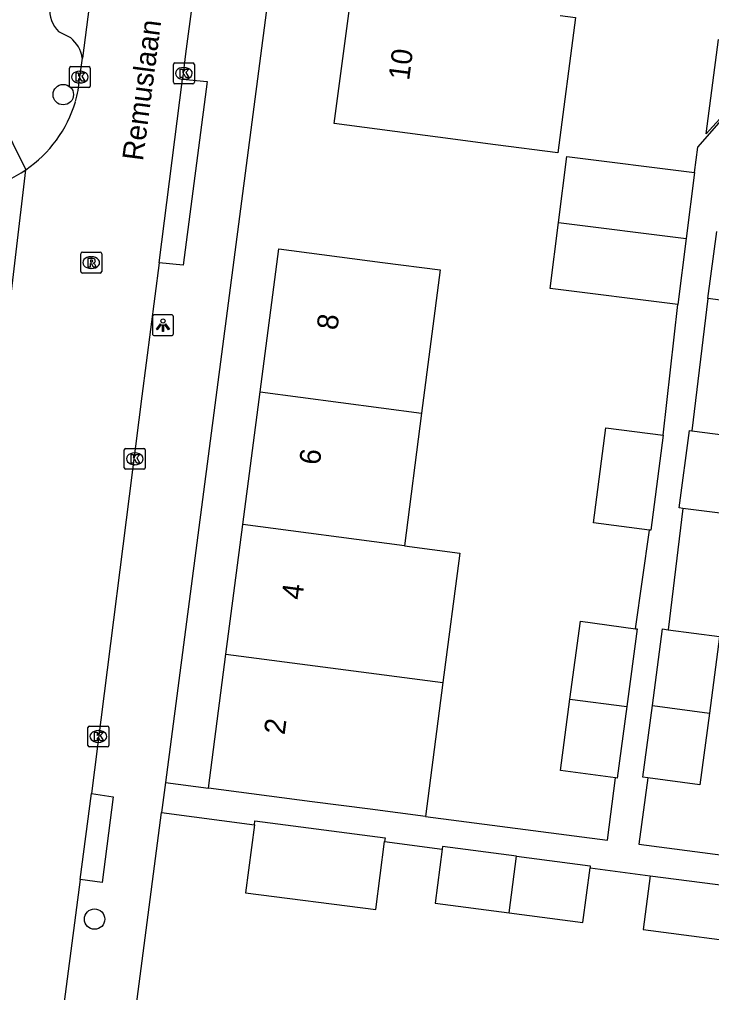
# Model space of a CAD drawing. Extents: x 162186 to 163152, y 385513 to 386513.
# Drawn here: x 162511.74 to 162544.83, y 386146.91 to 386193.42 of the extents above; entities that cross this region are included whole.
import ezdxf

# ---------------------------------------------------------------- set-up
doc = ezdxf.new("R2010")
doc.units = 0
for name, color, linetype in [('IMGEO_Boom', 7, 'Continuous'), ('IMGEO_Kolk', 7, 'Continuous'), ('IMGEO_Lichtpunt', 7, 'Continuous'), ('IMGEO_Openbare_ruimte_label', 7, 'Continuous'), ('IMGEO_Pand', 7, 'Continuous'), ('IMGEO_Pand_nummerreeks', 7, 'Continuous'), ('IMGEO_Rijbaan_lokaal_open', 7, 'Continuous'), ('IMGEO_Rioolput', 7, 'Continuous'), ('IMGEO_Voetpad_open', 7, 'Continuous')]:
    doc.layers.add(name, color=color, linetype=linetype)

msp = doc.modelspace()

# ---------------------------------------------------------------- linework, layer by layer
at = {"layer": 'IMGEO_Boom'}
for centre in [(162513.834, 386189.826), (162515.331, 386150.42)]:
    msp.add_circle(centre, 0.489, dxfattribs=at)
at = {"layer": 'IMGEO_Kolk'}
for p, q in [((162519.1, 386190.415), (162519.1, 386191.267)), ((162519.175, 386191.341), (162520.027, 386191.341)), ((162520.101, 386191.267), (162520.101, 386190.415)), ((162514.126, 386190.238), (162514.126, 386191.09)), ((162514.201, 386191.164), (162515.053, 386191.164)), ((162514.614, 386190.944), (162514.639, 386190.944)), ((162515.127, 386191.09), (162515.127, 386190.238)), ((162519.588, 386191.121), (162519.613, 386191.121)), ((162514.637, 386190.384), (162514.612, 386190.384)), ((162520.027, 386190.341), (162519.175, 386190.341)), ((162519.611, 386190.561), (162519.586, 386190.561)), ((162515.053, 386190.164), (162514.201, 386190.164)), ((162516.753, 386171.993), (162516.753, 386172.845)), ((162516.828, 386172.919), (162517.68, 386172.919)), ((162517.241, 386172.699), (162517.266, 386172.699)), ((162517.754, 386172.845), (162517.754, 386171.993)), ((162517.68, 386171.919), (162516.828, 386171.919)), ((162517.264, 386172.139), (162517.239, 386172.139)), ((162515.087, 386159.648), (162515.939, 386159.648)), ((162515.012, 386158.722), (162515.012, 386159.574)), ((162515.5, 386159.428), (162515.525, 386159.428)), ((162516.013, 386159.574), (162516.013, 386158.722)), ((162515.523, 386158.868), (162515.498, 386158.868)), ((162515.939, 386158.648), (162515.087, 386158.648))]:
    msp.add_line(p, q, dxfattribs=at)
for points in [[(162519.1, 386190.415), (162519.1, 386191.267)], [(162519.175, 386191.341), (162520.027, 386191.341)], [(162520.101, 386191.267), (162520.101, 386190.415)], [(162514.126, 386190.238), (162514.126, 386191.09)], [(162514.201, 386191.164), (162515.053, 386191.164)], [(162514.447, 386190.864), (162514.57, 386190.864), (162514.57, 386190.713), (162514.7, 386190.864), (162514.864, 386190.864), (162514.718, 386190.713), (162514.871, 386190.464), (162514.719, 386190.464), (162514.634, 386190.628), (162514.57, 386190.561), (162514.57, 386190.464), (162514.447, 386190.464), (162514.447, 386190.864)], [(162515.127, 386191.09), (162515.127, 386190.238)], [(162519.421, 386191.041), (162519.544, 386191.041), (162519.544, 386190.89), (162519.674, 386191.041), (162519.838, 386191.041), (162519.692, 386190.89), (162519.845, 386190.641), (162519.693, 386190.641), (162519.608, 386190.805), (162519.544, 386190.738), (162519.544, 386190.641), (162519.421, 386190.641), (162519.421, 386191.041)], [(162520.027, 386190.341), (162519.175, 386190.341)], [(162515.053, 386190.164), (162514.201, 386190.164)], [(162516.753, 386171.993), (162516.753, 386172.845)], [(162516.828, 386172.919), (162517.68, 386172.919)], [(162517.754, 386172.845), (162517.754, 386171.993)], [(162517.074, 386172.619), (162517.197, 386172.619), (162517.197, 386172.468), (162517.327, 386172.619), (162517.491, 386172.619), (162517.345, 386172.468), (162517.498, 386172.219), (162517.346, 386172.219), (162517.261, 386172.383), (162517.197, 386172.316), (162517.197, 386172.219), (162517.074, 386172.219), (162517.074, 386172.619)], [(162517.68, 386171.919), (162516.828, 386171.919)], [(162515.087, 386159.648), (162515.939, 386159.648)], [(162515.012, 386158.722), (162515.012, 386159.574)], [(162515.333, 386159.348), (162515.456, 386159.348), (162515.456, 386159.197), (162515.586, 386159.348), (162515.75, 386159.348), (162515.604, 386159.197), (162515.757, 386158.948), (162515.605, 386158.948), (162515.52, 386159.112), (162515.456, 386159.045), (162515.456, 386158.948), (162515.333, 386158.948), (162515.333, 386159.348)], [(162516.013, 386159.574), (162516.013, 386158.722)], [(162515.939, 386158.648), (162515.087, 386158.648)]]:
    msp.add_lwpolyline(points, dxfattribs=at)
for centre, start, end in [((162519.177, 386191.265), 91.552, 178.448), ((162519.177, 386191.265), 91.552, 178.448), ((162520.025, 386191.265), 1.552, 88.448), ((162520.025, 386191.265), 1.552, 88.448), ((162514.203, 386191.088), 91.552, 178.448), ((162514.203, 386191.088), 91.552, 178.448), ((162515.051, 386191.088), 1.552, 88.448), ((162515.051, 386191.088), 1.552, 88.448), ((162519.177, 386190.417), 181.552, 268.448), ((162519.177, 386190.417), 181.552, 268.448), ((162520.025, 386190.417), 271.552, 358.448), ((162520.025, 386190.417), 271.552, 358.448), ((162514.203, 386190.24), 181.552, 268.448), ((162514.203, 386190.24), 181.552, 268.448), ((162515.051, 386190.24), 271.552, 358.448), ((162515.051, 386190.24), 271.552, 358.448), ((162516.83, 386172.843), 91.552, 178.448), ((162516.83, 386172.843), 91.552, 178.448), ((162517.678, 386172.843), 1.552, 88.448), ((162517.678, 386172.843), 1.552, 88.448), ((162516.83, 386171.995), 181.552, 268.448), ((162516.83, 386171.995), 181.552, 268.448), ((162517.678, 386171.995), 271.552, 358.448), ((162517.678, 386171.995), 271.552, 358.448), ((162515.089, 386159.572), 91.552, 178.448), ((162515.089, 386159.572), 91.552, 178.448), ((162515.937, 386159.572), 1.552, 88.448), ((162515.937, 386159.572), 1.552, 88.448), ((162515.089, 386158.724), 181.552, 268.448), ((162515.089, 386158.724), 181.552, 268.448), ((162515.937, 386158.724), 271.552, 358.448), ((162515.937, 386158.724), 271.552, 358.448)]:
    msp.add_arc(centre, 0.0765, start, end, dxfattribs=at)
for centre, major_axis, ratio, start_param, end_param in [((162514.613, 386190.664), (-0.387, 0.002), 0.722429, 4.712389, 7.853982), ((162514.638, 386190.664), (-0.39, 0.002), 0.717154, 1.570796, 4.712389), ((162519.587, 386190.841), (-0.387, 0.002), 0.722429, 4.712389, 7.853982), ((162519.612, 386190.841), (-0.39, 0.002), 0.717154, 1.570796, 4.712389), ((162517.24, 386172.419), (-0.387, 0.002), 0.722429, 4.712389, 7.853982), ((162517.265, 386172.419), (-0.39, 0.002), 0.717154, 1.570796, 4.712389), ((162515.499, 386159.148), (-0.387, 0.002), 0.722429, 4.712389, 7.853982), ((162515.524, 386159.148), (-0.39, 0.002), 0.717154, 1.570796, 4.712389)]:
    msp.add_ellipse(centre, major_axis=major_axis, ratio=ratio, start_param=start_param, end_param=end_param, dxfattribs=at)
at = {"layer": 'IMGEO_Lichtpunt'}
for p, q in [((162518.101, 386179.21), (162518.101, 386178.403)), ((162518.101, 386179.21), (162518.101, 386178.403)), ((162519.003, 386179.305), (162518.195, 386179.305)), ((162519.003, 386179.305), (162518.195, 386179.305)), ((162519.097, 386178.403), (162519.097, 386179.21)), ((162519.097, 386178.403), (162519.097, 386179.21)), ((162518.195, 386178.309), (162519.003, 386178.309)), ((162518.195, 386178.309), (162519.003, 386178.309))]:
    msp.add_line(p, q, dxfattribs=at)
for points in [[(162518.475, 386178.874), (162518.514, 386178.846), (162518.326, 386178.584), (162518.288, 386178.611), (162518.475, 386178.874)], [(162518.577, 386178.826), (162518.624, 386178.826), (162518.624, 386178.504), (162518.577, 386178.504), (162518.577, 386178.826)], [(162518.687, 386178.846), (162518.725, 386178.873), (162518.912, 386178.611), (162518.873, 386178.583), (162518.687, 386178.846)]]:
    msp.add_lwpolyline(points, dxfattribs=at)
msp.add_circle((162518.6, 386179.008), 0.0994, dxfattribs=at)
for centre, start, end in [((162518.195, 386179.21), 90, 180), ((162518.195, 386179.21), 90, 180), ((162519.003, 386179.21), 0, 90), ((162519.003, 386179.21), 0, 90), ((162518.195, 386178.403), 180, 270), ((162518.195, 386178.403), 180, 270), ((162519.003, 386178.403), 270, 0), ((162519.003, 386178.403), 270, 360)]:
    msp.add_arc(centre, 0.0946, start, end, dxfattribs=at)
at = {"layer": 'IMGEO_Pand'}
for points in [[(162537.591, 386193.606), (162538.33, 386193.508), (162537.477, 386187.042), (162534.503, 386187.434), (162531.75, 386187.797), (162526.792, 386188.451), (162527.645, 386194.92)], [(162545.165, 386192.456), (162548.301, 386192.043), (162544.57, 386187.949), (162545.165, 386192.456)], [(162537.508, 386183.72), (162537.906, 386186.873), (162544.02, 386186.101)], [(162544.02, 386186.101), (162543.622, 386182.948)], [(162543.224, 386179.795), (162537.109, 386180.566), (162537.508, 386183.72)], [(162537.508, 386183.72), (162543.622, 386182.948)], [(162543.622, 386182.948), (162543.224, 386179.795)], [(162544.651, 386180.089), (162545.075, 386183.285)], [(162523.245, 386175.621), (162524.136, 386182.455), (162529.095, 386181.809), (162531.86, 386181.449), (162530.969, 386174.608)], [(162551.156, 386182.506), (162550.729, 386179.284), (162544.651, 386180.089)], [(162522.419, 386169.278), (162523.245, 386175.621)], [(162523.245, 386175.621), (162530.969, 386174.608)], [(162530.969, 386174.608), (162530.143, 386168.265)], [(162541.861, 386169.01), (162539.187, 386169.359), (162539.778, 386173.899), (162542.516, 386173.543)], [(162543.449, 386170.052), (162543.287, 386170.073), (162543.768, 386173.769), (162543.892, 386173.753)], [(162543.892, 386173.753), (162546.479, 386173.416), (162545.998, 386169.72), (162543.449, 386170.052)], [(162542.516, 386173.543), (162541.924, 386169.002), (162541.861, 386169.01)], [(162521.612, 386163.089), (162522.419, 386169.278)], [(162530.143, 386168.265), (162522.419, 386169.278)], [(162530.143, 386168.265), (162532.792, 386167.917), (162531.986, 386161.729)], [(162538.06, 386160.933), (162538.56, 386164.653), (162541.2, 386164.298)], [(162541.2, 386164.298), (162541.275, 386164.288), (162540.776, 386160.577)], [(162541.999, 386160.635), (162542.49, 386164.288), (162542.755, 386164.252)], [(162542.755, 386164.252), (162545.214, 386163.922), (162544.723, 386160.268)], [(162520.777, 386156.678), (162521.612, 386163.089)], [(162521.612, 386163.089), (162531.986, 386161.729)], [(162531.986, 386161.729), (162531.152, 386155.327)], [(162540.242, 386157.169), (162537.602, 386157.524), (162538.06, 386160.933)], [(162538.06, 386160.933), (162540.776, 386160.577)], [(162540.776, 386160.577), (162540.316, 386157.159), (162540.242, 386157.169)], [(162541.784, 386157.169), (162541.538, 386157.202), (162541.999, 386160.635)], [(162541.999, 386160.635), (162544.723, 386160.268)], [(162544.723, 386160.268), (162544.261, 386156.836), (162541.784, 386157.169)], [(162531.152, 386155.327), (162528.502, 386155.672), (162525.736, 386156.032), (162520.777, 386156.678)], [(162522.973, 386154.932), (162522.996, 386155.112), (162529.217, 386154.302), (162529.194, 386154.125)], [(162522.973, 386154.932), (162522.549, 386151.683), (162528.77, 386150.873), (162529.194, 386154.125)], [(162531.95, 386153.769), (162531.613, 386151.185), (162535.146, 386150.725)], [(162535.499, 386153.431), (162531.966, 386153.891), (162531.95, 386153.769)], [(162535.146, 386150.725), (162535.499, 386153.431)], [(162535.499, 386153.431), (162539.032, 386152.971), (162539.018, 386152.863)], [(162535.146, 386150.725), (162538.679, 386150.265), (162539.018, 386152.863)], [(162541.897, 386152.494), (162541.562, 386149.918), (162547.15, 386149.19), (162547.486, 386151.766)], [(162541.897, 386152.494), (162547.486, 386151.766)]]:
    msp.add_lwpolyline(points, dxfattribs=at)
at = {"layer": 'IMGEO_Rijbaan_lokaal_open'}
for points in [[(162520.569, 386236.666), (162514.746, 386191.574)], [(162525.592, 386235.986), (162519.686, 386191.776), (162519.542, 386190.566)], [(162514.616, 386190.567), (162514.746, 386191.574)], [(162518.419, 386181.789), (162519.542, 386190.566)], [(162510.578, 386173.939), (162512.043, 386186.234)], [(162518.419, 386181.789), (162517.587, 386175.419), (162515.183, 386156.42)], [(162514.645, 386152.313), (162515.183, 386156.42)], [(162514.645, 386152.313), (162511.491, 386128.213)]]:
    msp.add_lwpolyline(points, dxfattribs=at)
for centre, radius, start, end in [((162508.101, 386191.214), 6.547, 344.7332, 354.3296), ((162508.655, 386191.197), 6.009, 304.3137, 343.4935), ((162508.655, 386191.195), 6.007, 265.1401, 304.3325)]:
    msp.add_arc(centre, radius, start, end, dxfattribs=at)
at = {"layer": 'IMGEO_Rioolput'}
for p, q in [((162514.671, 386181.372), (162514.671, 386182.224)), ((162514.746, 386182.298), (162515.598, 386182.298)), ((162515.159, 386182.078), (162515.184, 386182.078)), ((162515.672, 386182.224), (162515.672, 386181.372)), ((162515.182, 386181.518), (162515.157, 386181.518)), ((162515.598, 386181.298), (162514.746, 386181.298))]:
    msp.add_line(p, q, dxfattribs=at)
for points in [[(162514.671, 386181.372), (162514.671, 386182.224)], [(162514.746, 386182.298), (162515.598, 386182.298)], [(162515.26, 386181.996), (162515.008, 386181.998), (162515.008, 386181.598)], [(162515.672, 386182.224), (162515.672, 386181.372)], [(162515.008, 386181.598), (162515.132, 386181.598), (162515.132, 386181.76), (162515.143, 386181.76)], [(162515.186, 386181.917), (162515.132, 386181.917), (162515.132, 386181.836)], [(162515.132, 386181.836), (162515.184, 386181.836)], [(162515.19, 386181.731), (162515.261, 386181.598), (162515.401, 386181.598), (162515.336, 386181.724)], [(162515.598, 386181.298), (162514.746, 386181.298)]]:
    msp.add_lwpolyline(points, dxfattribs=at)
for centre, radius, start, end in [((162514.748, 386182.222), 0.0765, 91.552, 178.448), ((162514.748, 386182.222), 0.0765, 91.552, 178.448), ((162515.259, 386181.886), 0.109, 350.3612, 89.416), ((162515.596, 386182.222), 0.0765, 1.552, 88.448), ((162515.596, 386182.222), 0.0765, 1.552, 88.448), ((162515.142, 386181.707), 0.0533, 26.0293, 88.6989), ((162515.168, 386182.025), 0.19, 274.7715, 282.9687), ((162515.192, 386181.821), 0.0964, 77.0061, 93.1865), ((162515.206, 386181.878), 0.0378, 276.6634, 79.6772), ((162515.257, 386181.886), 0.112, 277.5842, 350.9817), ((162515.241, 386181.671), 0.108, 29.5134, 73.7905), ((162514.748, 386181.374), 0.0765, 181.552, 268.448), ((162514.748, 386181.374), 0.0765, 181.552, 268.448), ((162515.596, 386181.374), 0.0765, 271.552, 358.448), ((162515.596, 386181.374), 0.0765, 271.552, 358.448)]:
    msp.add_arc(centre, radius, start, end, dxfattribs=at)
for centre, major_axis, ratio, start_param, end_param in [((162515.158, 386181.798), (-0.387, 0.002), 0.722429, 4.712389, 7.853982), ((162515.183, 386181.798), (-0.39, 0.002), 0.717154, 1.570796, 4.712389)]:
    msp.add_ellipse(centre, major_axis=major_axis, ratio=ratio, start_param=start_param, end_param=end_param, dxfattribs=at)
at = {"layer": 'IMGEO_Voetpad_open'}
for points in [[(162527.746, 386251.794), (162529.167, 386250), (162530.299, 386247.954), (162530.386, 386246.165), (162518.722, 386156.946)], [(162544.02, 386186.101), (162544.174, 386187.322), (162548.452, 386192.209), (162548.971, 386193.454), (162549.13, 386194.83)], [(162514.191, 386192.534), (162513.63, 386192.833)], [(162519.542, 386190.566), (162520.721, 386190.459), (162519.569, 386181.682), (162518.419, 386181.789)], [(162510.792, 386188.743), (162512.043, 386186.234)], [(162544.651, 386180.089), (162543.892, 386173.753)], [(162542.516, 386173.543), (162543.224, 386179.795)], [(162543.449, 386170.052), (162542.755, 386164.252)], [(162541.2, 386164.298), (162541.861, 386169.01)], [(162518.722, 386156.946), (162518.534, 386155.508)], [(162518.722, 386156.946), (162520.777, 386156.678)], [(162531.152, 386155.327), (162539.848, 386154.195), (162540.242, 386157.169)], [(162541.784, 386157.169), (162541.35, 386154.002), (162553.034, 386152.476)], [(162515.183, 386156.42), (162516.222, 386156.271), (162515.686, 386152.177), (162514.645, 386152.313)], [(162514.923, 386127.892), (162518.534, 386155.508)], [(162518.534, 386155.508), (162522.973, 386154.932)], [(162529.194, 386154.125), (162531.95, 386153.769)], [(162539.018, 386152.863), (162541.897, 386152.494)]]:
    msp.add_lwpolyline(points, dxfattribs=at)
for centre, radius, start, end in [((162514.595, 386193.872), 1.418, 173.9303, 227.1079), ((162513.198, 386191.32), 1.568, 9.3296, 50.737)]:
    msp.add_arc(centre, radius, start, end, dxfattribs=at)

# ---------------------------------------------------------------- texts
at = {"layer": 'IMGEO_Openbare_ruimte_label'}
msp.add_text('Remuslaan', height=1, rotation=82.5266, dxfattribs=at).set_placement((162517.64, 386186.628))
at = {"layer": 'IMGEO_Pand_nummerreeks'}
for s, rotation, p in [('10', 82.4898, (162530.367, 386190.473)), ('8', 82.5756, (162526.934, 386178.54)), ('6', 82.5756, (162526.094, 386172.092)), ('4', 82.5756, (162525.254, 386165.648)), ('2', 82.5756, (162524.414, 386159.201))]:
    msp.add_text(s, height=1, rotation=rotation, dxfattribs=at).set_placement(p)

doc.saveas('drawing.dxf')
